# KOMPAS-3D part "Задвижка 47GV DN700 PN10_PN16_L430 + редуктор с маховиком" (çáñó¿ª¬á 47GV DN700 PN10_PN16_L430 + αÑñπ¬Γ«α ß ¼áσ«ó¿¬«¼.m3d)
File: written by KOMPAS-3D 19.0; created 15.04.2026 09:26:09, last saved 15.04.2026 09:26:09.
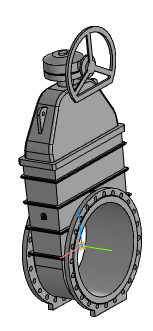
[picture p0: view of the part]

Document properties: Автор: Энергия; Полное имя файла: ..\..\Задвижка 47GV DN700 PN10_PN16_L390 + редуктор с маховиком.a3d

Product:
- Part/product: Задвижка 47GV DN700 PN10_PN16_L430 + редуктор с маховиком
    Масса: 2071.23

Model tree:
1. Операция без истории:1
